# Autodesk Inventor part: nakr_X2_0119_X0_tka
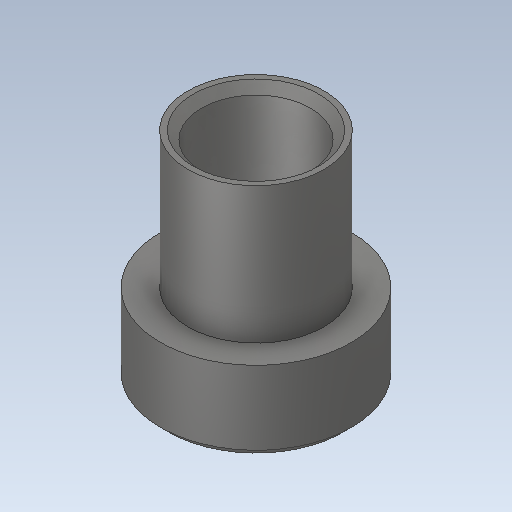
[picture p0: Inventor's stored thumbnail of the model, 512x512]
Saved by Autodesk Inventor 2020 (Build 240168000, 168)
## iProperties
Created: 2015-11
Part Number: nakr_X2_0119_X0_tka
Material: Ogólny
Document SubType Name: Modeling
Designer: Tomasz
Density: 1 g/cm^3
Appearance: Domyślna
Sending System: SolidWorks 2017
Last Author: Tomasz
Last Saved: 2017-11-19
Author: Tomasz
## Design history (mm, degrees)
feature "Imported1"
node "Bryła1"
